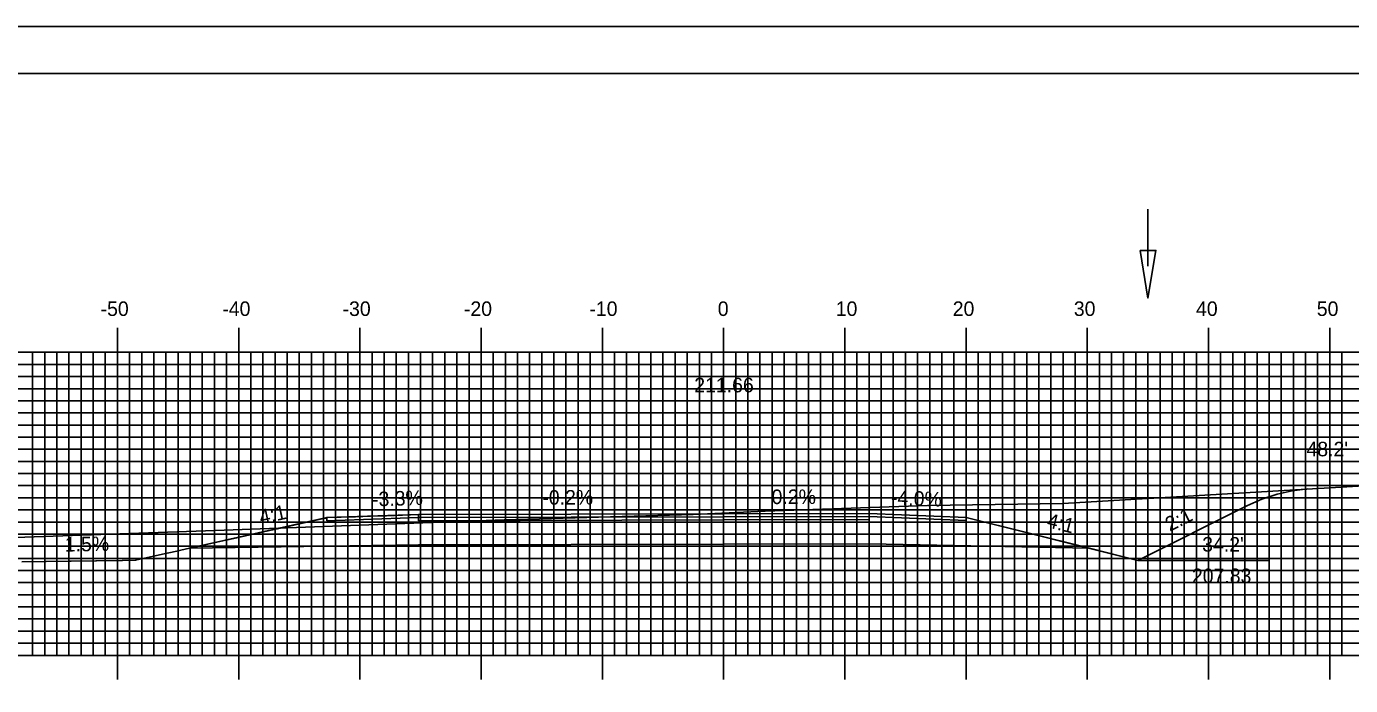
# Model space of a CAD drawing. Extents: x 853316 to 853659, y 364785 to 365005.
# Drawn here: x 853424.3 to 853533.5, y 364950.7 to 365005.1 of the extents above; entities that cross this region are included whole.
import ezdxf

# ---------------------------------------------------------------- set-up
doc = ezdxf.new("R2010")
doc.units = 0
for name, color, linetype in [('ANNOTATION', 7, 'Continuous'), ('BORDER', 7, 'Continuous'), ('D_Drainage_Ditch_Line', 7, 'Continuous'), ('D_Roadway_Centerline', 7, 'Continuous'), ('D_Roadway_Centerline_Text', 7, 'Continuous'), ('D_Roadway_Edge_Shoulder', 7, 'Continuous'), ('D_Roadway_Edge_TW', 7, 'Continuous'), ('D_Roadway_Pavement', 7, 'Continuous'), ('D_Roadway_SlopeLines', 7, 'Continuous'), ('D_Roadway_SubGrade', 7, 'Continuous'), ('D_Text_Standard', 7, 'Continuous'), ('H_V ANNOTATION', 7, 'Continuous'), ('MAJOR', 7, 'Continuous'), ('MINOR', 7, 'Continuous'), ('PDRAIN', 7, 'Continuous'), ('PLOT BOUNDARY', 7, 'Continuous'), ('S_Roadway_Centerline', 7, 'Continuous')]:
    doc.layers.add(name, color=color, linetype=linetype)

msp = doc.modelspace()

# ---------------------------------------------------------------- linework, layer by layer
at = {"layer": 'BORDER'}
msp.add_lwpolyline([(853332.16, 364791.23), (853652.16, 364791.23), (853652.16, 365001.23), (853332.16, 365001.23)], close=True, dxfattribs=at)
at = {"layer": 'D_Drainage_Ditch_Line'}
msp.add_line((853516.76, 364985.33), (853516.76, 364990.03), dxfattribs=at)
msp.add_lwpolyline([(853516.11, 364986.64), (853517.42, 364986.64), (853516.76, 364982.71)], close=True, dxfattribs=at)
at = {"layer": 'D_Roadway_Centerline'}
msp.add_lwpolyline([(853423.87, 364960.94), (853425.75, 364960.96), (853425.88, 364960.97), (853427.84, 364960.99), (853427.93, 364961), (853429.98, 364961.03), (853430.03, 364961.03), (853432.16, 364961.06), (853432.18, 364961.06), (853433.26, 364961.07), (853434, 364961.24), (853434.39, 364961.32), (853435.49, 364961.57), (853436.65, 364961.82), (853437, 364961.9), (853437.71, 364962.06), (853438.74, 364962.29), (853438.97, 364962.34), (853440.69, 364962.72), (853441.35, 364962.87), (853442.67, 364963.16), (853443.79, 364963.41), (853444.71, 364963.62), (853446.3, 364963.98), (853446.79, 364964.08), (853448.89, 364964.56), (853448.91, 364964.56), (853449.04, 364964.59), (853451.39, 364964.67), (853452.63, 364964.71), (853453.95, 364964.75), (853456.59, 364964.84), (853481.76, 364964.9), (853493.76, 364964.93), (853501.76, 364964.61), (853511.93, 364962.06), (853515.93, 364961.06), (853524.92, 364965.56), (853526.17, 364966.11), (853527.42, 364966.53), (853528.67, 364966.81), (853529.92, 364966.96)], dxfattribs=at)
at = {"layer": 'D_Roadway_Edge_Shoulder'}
for points in [[(853456.59, 364964.84), (853449.04, 364964.59), (853449.04, 364964.34), (853456.59, 364964.59)], [(853493.76, 364964.93), (853501.76, 364964.61), (853501.76, 364964.36), (853493.76, 364964.68)]]:
    msp.add_lwpolyline(points, close=True, dxfattribs=at)
at = {"layer": 'D_Roadway_Edge_TW'}
msp.add_lwpolyline([(853456.59, 364964.59), (853456.59, 364964.84), (853481.76, 364964.9), (853493.76, 364964.93), (853493.76, 364964.68), (853481.76, 364964.65)], close=True, dxfattribs=at)
at = {"layer": 'D_Roadway_Pavement'}
msp.add_lwpolyline([(853456.59, 364964.34), (853456.59, 364964.59), (853481.76, 364964.65), (853493.76, 364964.68), (853493.76, 364964.43), (853481.76, 364964.4)], close=True, dxfattribs=at)
at = {"layer": 'D_Roadway_SlopeLines'}
for points in [[(853515.93, 364961.06), (853524.92, 364965.56), (853526.17, 364966.11), (853527.42, 364966.53), (853528.67, 364966.81), (853529.92, 364966.96)], [(853501.76, 364964.61), (853515.93, 364961.06)]]:
    msp.add_lwpolyline(points, dxfattribs=at)
at = {"layer": 'D_Roadway_SubGrade'}
msp.add_lwpolyline([(853456.59, 364962.34), (853437.71, 364962.06), (853449.04, 364964.59), (853449.04, 364964.34), (853456.59, 364964.59), (853481.76, 364964.65), (853493.76, 364964.68), (853501.76, 364964.36), (853501.76, 364964.61), (853511.93, 364962.06), (853493.76, 364962.43), (853481.76, 364962.4)], close=True, dxfattribs=at)
at = {"layer": 'MAJOR'}
for p, q in [((853431.76, 364980.24), (853431.76, 364978.23)), ((853441.76, 364980.24), (853441.76, 364978.23)), ((853451.76, 364980.24), (853451.76, 364978.23)), ((853461.76, 364980.24), (853461.76, 364978.23)), ((853471.76, 364980.24), (853471.76, 364978.23)), ((853481.76, 364980.24), (853481.76, 364978.23)), ((853491.76, 364980.24), (853491.76, 364978.23)), ((853501.76, 364980.24), (853501.76, 364978.23)), ((853511.76, 364980.24), (853511.76, 364978.23)), ((853521.76, 364980.24), (853521.76, 364978.23)), ((853531.76, 364980.24), (853531.76, 364978.23)), ((853341.76, 364978.23), (853621.76, 364978.23)), ((853341.76, 364978.23), (853621.76, 364978.23)), ((853431.76, 364953.23), (853431.76, 364978.23)), ((853441.76, 364953.23), (853441.76, 364978.23)), ((853451.76, 364953.23), (853451.76, 364978.23)), ((853461.76, 364953.23), (853461.76, 364978.23)), ((853471.76, 364953.23), (853471.76, 364978.23)), ((853481.76, 364953.23), (853481.76, 364978.23)), ((853491.76, 364953.23), (853491.76, 364978.23)), ((853501.76, 364953.23), (853501.76, 364978.23)), ((853511.76, 364953.23), (853511.76, 364978.23)), ((853521.76, 364953.23), (853521.76, 364978.23)), ((853531.76, 364953.23), (853531.76, 364978.23)), ((853341.76, 364973.23), (853621.76, 364973.23)), ((853341.76, 364968.23), (853621.76, 364968.23)), ((853341.76, 364963.23), (853621.76, 364963.23)), ((853341.76, 364958.23), (853621.76, 364958.23)), ((853341.76, 364953.23), (853621.76, 364953.23)), ((853341.76, 364953.23), (853621.76, 364953.23)), ((853431.76, 364951.23), (853431.76, 364953.23)), ((853441.76, 364951.23), (853441.76, 364953.23)), ((853451.76, 364951.23), (853451.76, 364953.23)), ((853461.76, 364951.23), (853461.76, 364953.23)), ((853471.76, 364951.23), (853471.76, 364953.23)), ((853481.76, 364951.23), (853481.76, 364953.23)), ((853491.76, 364951.23), (853491.76, 364953.23)), ((853501.76, 364951.23), (853501.76, 364953.23)), ((853511.76, 364951.23), (853511.76, 364953.23)), ((853521.76, 364951.23), (853521.76, 364953.23)), ((853531.76, 364951.23), (853531.76, 364953.23))]:
    msp.add_line(p, q, dxfattribs=at)
at = {"layer": 'MINOR'}
for p, q in [((853424.76, 364953.23), (853424.76, 364978.23)), ((853425.76, 364953.23), (853425.76, 364978.23)), ((853426.76, 364953.23), (853426.76, 364978.23)), ((853427.76, 364953.23), (853427.76, 364978.23)), ((853428.76, 364953.23), (853428.76, 364978.23)), ((853429.76, 364953.23), (853429.76, 364978.23)), ((853430.76, 364953.23), (853430.76, 364978.23)), ((853432.76, 364953.23), (853432.76, 364978.23)), ((853433.76, 364953.23), (853433.76, 364978.23)), ((853434.76, 364953.23), (853434.76, 364978.23)), ((853435.76, 364953.23), (853435.76, 364978.23)), ((853436.76, 364953.23), (853436.76, 364978.23)), ((853437.76, 364953.23), (853437.76, 364978.23)), ((853438.76, 364953.23), (853438.76, 364978.23)), ((853439.76, 364953.23), (853439.76, 364978.23)), ((853440.76, 364953.23), (853440.76, 364978.23)), ((853442.76, 364953.23), (853442.76, 364978.23)), ((853443.76, 364953.23), (853443.76, 364978.23)), ((853444.76, 364953.23), (853444.76, 364978.23)), ((853445.76, 364953.23), (853445.76, 364978.23)), ((853446.76, 364953.23), (853446.76, 364978.23)), ((853447.76, 364953.23), (853447.76, 364978.23)), ((853448.76, 364953.23), (853448.76, 364978.23)), ((853449.76, 364953.23), (853449.76, 364978.23)), ((853450.76, 364953.23), (853450.76, 364978.23)), ((853452.76, 364953.23), (853452.76, 364978.23)), ((853453.76, 364953.23), (853453.76, 364978.23)), ((853454.76, 364953.23), (853454.76, 364978.23)), ((853455.76, 364953.23), (853455.76, 364978.23)), ((853456.76, 364953.23), (853456.76, 364978.23)), ((853457.76, 364953.23), (853457.76, 364978.23)), ((853458.76, 364953.23), (853458.76, 364978.23)), ((853459.76, 364953.23), (853459.76, 364978.23)), ((853460.76, 364953.23), (853460.76, 364978.23)), ((853462.76, 364953.23), (853462.76, 364978.23)), ((853463.76, 364953.23), (853463.76, 364978.23)), ((853464.76, 364953.23), (853464.76, 364978.23)), ((853465.76, 364953.23), (853465.76, 364978.23)), ((853466.76, 364953.23), (853466.76, 364978.23)), ((853467.76, 364953.23), (853467.76, 364978.23)), ((853468.76, 364953.23), (853468.76, 364978.23)), ((853469.76, 364953.23), (853469.76, 364978.23)), ((853470.76, 364953.23), (853470.76, 364978.23)), ((853472.76, 364953.23), (853472.76, 364978.23)), ((853473.76, 364953.23), (853473.76, 364978.23)), ((853474.76, 364953.23), (853474.76, 364978.23)), ((853475.76, 364953.23), (853475.76, 364978.23)), ((853476.76, 364953.23), (853476.76, 364978.23)), ((853477.76, 364953.23), (853477.76, 364978.23)), ((853478.76, 364953.23), (853478.76, 364978.23)), ((853479.76, 364953.23), (853479.76, 364978.23)), ((853480.76, 364953.23), (853480.76, 364978.23)), ((853482.76, 364953.23), (853482.76, 364978.23)), ((853483.76, 364953.23), (853483.76, 364978.23)), ((853484.76, 364953.23), (853484.76, 364978.23)), ((853485.76, 364953.23), (853485.76, 364978.23)), ((853486.76, 364953.23), (853486.76, 364978.23)), ((853487.76, 364953.23), (853487.76, 364978.23)), ((853488.76, 364953.23), (853488.76, 364978.23)), ((853489.76, 364953.23), (853489.76, 364978.23)), ((853490.76, 364953.23), (853490.76, 364978.23)), ((853492.76, 364953.23), (853492.76, 364978.23)), ((853493.76, 364953.23), (853493.76, 364978.23)), ((853494.76, 364953.23), (853494.76, 364978.23)), ((853495.76, 364953.23), (853495.76, 364978.23)), ((853496.76, 364953.23), (853496.76, 364978.23)), ((853497.76, 364953.23), (853497.76, 364978.23)), ((853498.76, 364953.23), (853498.76, 364978.23)), ((853499.76, 364953.23), (853499.76, 364978.23)), ((853500.76, 364953.23), (853500.76, 364978.23)), ((853502.76, 364953.23), (853502.76, 364978.23)), ((853503.76, 364953.23), (853503.76, 364978.23)), ((853504.76, 364953.23), (853504.76, 364978.23)), ((853505.76, 364953.23), (853505.76, 364978.23)), ((853506.76, 364953.23), (853506.76, 364978.23)), ((853507.76, 364953.23), (853507.76, 364978.23)), ((853508.76, 364953.23), (853508.76, 364978.23)), ((853509.76, 364953.23), (853509.76, 364978.23)), ((853510.76, 364953.23), (853510.76, 364978.23)), ((853512.76, 364953.23), (853512.76, 364978.23)), ((853513.76, 364953.23), (853513.76, 364978.23)), ((853514.76, 364953.23), (853514.76, 364978.23)), ((853515.76, 364953.23), (853515.76, 364978.23)), ((853516.76, 364953.23), (853516.76, 364978.23)), ((853517.76, 364953.23), (853517.76, 364978.23)), ((853518.76, 364953.23), (853518.76, 364978.23)), ((853519.76, 364953.23), (853519.76, 364978.23)), ((853520.76, 364953.23), (853520.76, 364978.23)), ((853522.76, 364953.23), (853522.76, 364978.23)), ((853523.76, 364953.23), (853523.76, 364978.23)), ((853524.76, 364953.23), (853524.76, 364978.23)), ((853525.76, 364953.23), (853525.76, 364978.23)), ((853526.76, 364953.23), (853526.76, 364978.23)), ((853527.76, 364953.23), (853527.76, 364978.23)), ((853528.76, 364953.23), (853528.76, 364978.23)), ((853529.76, 364953.23), (853529.76, 364978.23)), ((853530.76, 364953.23), (853530.76, 364978.23)), ((853532.76, 364953.23), (853532.76, 364978.23)), ((853341.76, 364977.23), (853621.76, 364977.23)), ((853341.76, 364976.23), (853621.76, 364976.23)), ((853341.76, 364975.23), (853621.76, 364975.23)), ((853341.76, 364974.23), (853621.76, 364974.23)), ((853341.76, 364972.23), (853621.76, 364972.23)), ((853341.76, 364971.23), (853621.76, 364971.23)), ((853341.76, 364970.23), (853621.76, 364970.23)), ((853341.76, 364969.23), (853621.76, 364969.23)), ((853341.76, 364967.23), (853621.76, 364967.23)), ((853341.76, 364966.23), (853621.76, 364966.23)), ((853341.76, 364965.23), (853621.76, 364965.23)), ((853341.76, 364964.23), (853621.76, 364964.23)), ((853341.76, 364962.23), (853621.76, 364962.23)), ((853341.76, 364961.23), (853621.76, 364961.23)), ((853341.76, 364960.23), (853621.76, 364960.23)), ((853341.76, 364959.23), (853621.76, 364959.23)), ((853341.76, 364957.23), (853621.76, 364957.23)), ((853341.76, 364956.23), (853621.76, 364956.23)), ((853341.76, 364955.23), (853621.76, 364955.23)), ((853341.76, 364954.23), (853621.76, 364954.23))]:
    msp.add_line(p, q, dxfattribs=at)
at = {"layer": 'PDRAIN'}
msp.add_line((853515.93, 364961.06), (853526.7, 364961.06), dxfattribs=at)
at = {"layer": 'PLOT BOUNDARY'}
msp.add_lwpolyline([(853315.97, 364785.11), (853655.97, 364785.11), (853655.97, 365005.11), (853315.97, 365005.11)], close=True, dxfattribs=at)
at = {"layer": 'S_Roadway_Centerline'}
msp.add_lwpolyline([(853341.76, 364960.71), (853345.93, 364960.83), (853353.35, 364961.01), (853361.55, 364961.33), (853402.27, 364962.38), (853412.31, 364962.57), (853439.83, 364963.53), (853463.65, 364964.4), (853479.24, 364964.85), (853485.19, 364965.12), (853498.57, 364965.58), (853509.74, 364965.76), (853537.83, 364967.42), (853541.41, 364967.63), (853545.3, 364967.83), (853560.67, 364968.6), (853562.25, 364968.66), (853577.65, 364969.22), (853583.69, 364969.65), (853594.37, 364970.31), (853607.63, 364971.07), (853621.76, 364971.89)], dxfattribs=at)

# ---------------------------------------------------------------- texts
at = {"layer": 'ANNOTATION'}
for s, rotation, p in [('-3.3%', 1.8989, (853452.78, 364965.51)), ('-0.2%', 0.1323, (853466.81, 364965.66)), ('0.2%', 0.1323, (853485.72, 364965.71)), ('-4.0%', 357.7094, (853495.55, 364965.66)), ('4:1', 12.6747, (853443.6, 364964.02)), ('4:1', 345.9638, (853508.35, 364963.82)), ('2:1', 26.5651, (853518.57, 364963.42)), ('-1.5%', 0.8407, (853426.89, 364961.78))]:
    msp.add_text(s, height=1.2, rotation=rotation, dxfattribs=at).set_placement(p)
for s, p in [("34.2'", (853521.24, 364961.79)), ('207.83', (853520.39, 364959.19))]:
    msp.add_text(s, height=1.2, dxfattribs=at).set_placement(p)
at = {"layer": 'D_Roadway_Centerline'}
for s, p in [('C', (853481.75, 364964.9)), ('L', (853481.76, 364964.89))]:
    msp.add_text(s, height=0.0146, dxfattribs=at).set_placement(p)
at = {"layer": 'D_Roadway_Centerline_Text'}
msp.add_text('211.66', height=1.2, dxfattribs=at).set_placement((853479.34, 364974.93))
at = {"layer": 'D_Text_Standard'}
msp.add_text("48.2'", height=1.2, dxfattribs=at).set_placement((853529.84, 364969.65))
at = {"layer": 'H_V ANNOTATION'}
for s, p in [('-50', (853430.37, 364981.23)), ('-40', (853440.41, 364981.23)), ('-30', (853450.33, 364981.23)), ('-20', (853460.34, 364981.23)), ('-10', (853470.69, 364981.23)), ('0', (853481.28, 364981.23)), ('10', (853491.01, 364981.23)), ('20', (853500.66, 364981.23)), ('30', (853510.65, 364981.23)), ('40', (853520.73, 364981.23)), ('50', (853530.69, 364981.23))]:
    msp.add_text(s, height=1.2, dxfattribs=at).set_placement(p)

doc.saveas('drawing.dxf')
